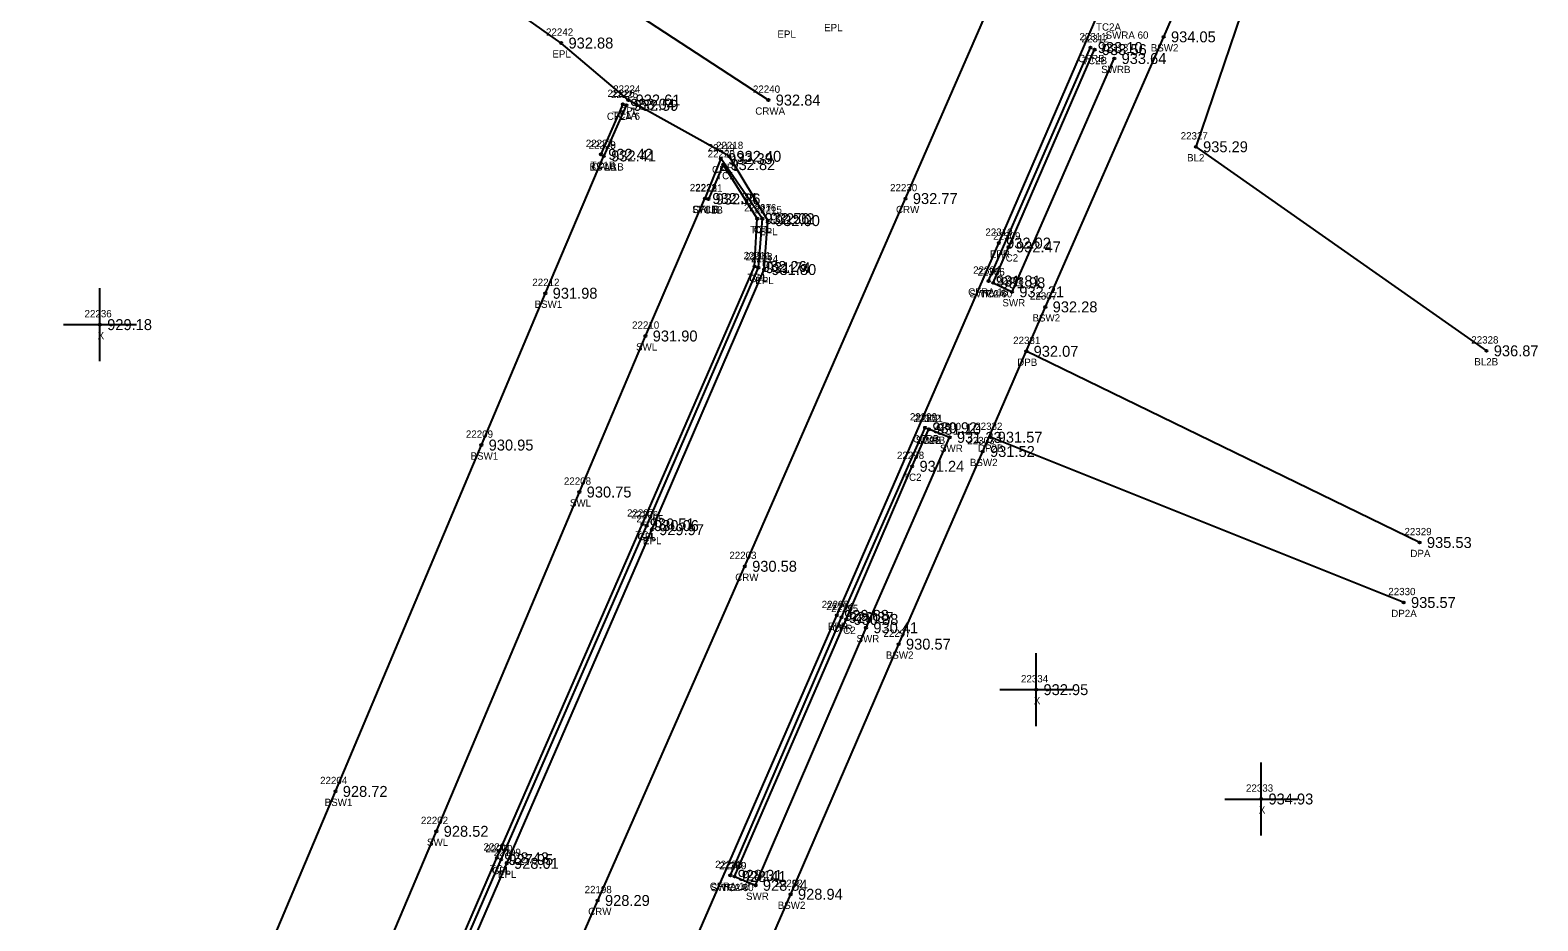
# Model space of a CAD drawing. Extents: x 1576181 to 1577685, y 1099396 to 1101490.
# Drawn here: x 1577213.8 to 1577420.4, y 1101221.4 to 1101343.5 of the extents above; entities that cross this region are included whole.
import ezdxf

# ---------------------------------------------------------------- set-up
doc = ezdxf.new("R2010")
doc.units = 0
for name, color, linetype in [('RD_DTM_BkLn1', 7, 'Continuous'), ('RD_DTM_BkLn2', 7, 'Continuous'), ('RD_DTM_BkLn_txCode', 7, 'Continuous'), ('RD_EX_Conc', 7, 'Continuous'), ('RD_EX_Conc_txCode', 7, 'Continuous'), ('RD_EX_Driveway', 7, 'Continuous'), ('RD_EX_Driveway_txCode', 7, 'Continuous'), ('RD_EX_Misc', 7, 'Continuous'), ('RD_EX_Misc_txCode', 7, 'Continuous'), ('RD_EX_Road', 7, 'Continuous'), ('RD_EX_Road_txCode', 7, 'Continuous'), ('RD_EX_TX_Conc_ELEV', 7, 'Continuous'), ('RD_EX_TX_Driveway_ELEV', 7, 'Continuous'), ('RD_EX_TX_Misc_ELEV', 7, 'Continuous'), ('RD_EX_TX_Road_ELEV', 7, 'Continuous'), ('RD_HC_Survey_ELEV', 7, 'Continuous'), ('RD_HC_Survey_txCode', 7, 'Continuous'), ('RD_SMD_Locator', 7, 'Continuous')]:
    doc.layers.add(name, color=color, linetype=linetype)

msp = doc.modelspace()

# ---------------------------------------------------------------- linework, layer by layer
at = {"layer": 'RD_DTM_BkLn1'}
for points in [[(1577315, 1101333.96), (1577292.13, 1101348.94), (1577251.18, 1101377.2), (1577210.87, 1101406.3), (1577169.7, 1101434.76), (1577128.91, 1101464.09)], [(1576908.25, 1100441.74), (1576920.44, 1100463.64), (1576944.47, 1100507.42), (1576973.89, 1100560.12), (1576993.13, 1100594.33), (1577014.77, 1100632.79), (1577042.14, 1100681.68), (1577066.82, 1100725.12), (1577089.75, 1100766.04), (1577111.87, 1100810.02), (1577132.74, 1100857.48), (1577152.58, 1100903.02), (1577172.32, 1100949.02), (1577191.93, 1100994.6), (1577211.77, 1101040.76), (1577222.24, 1101065.99), (1577231.17, 1101086.4), (1577251.41, 1101132.37), (1577271.56, 1101178.18), (1577291.61, 1101224.24), (1577311.77, 1101270.05), (1577333.79, 1101320.46), (1577355.93, 1101371.29), (1577365.01, 1101392.03)], [(1577390.63, 1101377.85), (1577373.56, 1101327.56), (1577413.39, 1101299.59)]]:
    msp.add_lwpolyline(points, dxfattribs=at)
at = {"layer": 'RD_DTM_BkLn2'}
msp.add_line((1577295.05, 1101333.39), (1577292.05, 1101326.53), dxfattribs=at)
for points in [[(1577345.79, 1101308.91), (1577347.93, 1101313.83), (1577359.7, 1101340.88)], [(1577230.41, 1101120.92), (1577237.86, 1101138.09), (1577257.81, 1101183.92), (1577277.8, 1101230.08), (1577297.74, 1101275.86), (1577313.11, 1101311.15), (1577313.47, 1101317.71), (1577308.8, 1101325.11), (1577306.78, 1101320.4)], [(1577310.35, 1101227.52), (1577325.67, 1101262.77), (1577334.7, 1101283.76), (1577336.99, 1101288.83)]]:
    msp.add_lwpolyline(points, dxfattribs=at)
at = {"layer": 'RD_EX_Conc'}
for p, q in [((1577345.17, 1101309.16), (1577359.13, 1101341.16)), ((1577295.52, 1101333.24), (1577292.45, 1101326.3))]:
    msp.add_line(p, q, dxfattribs=at)
for points in [[(1577253.83, 1101078.11), (1577273.62, 1101123.24), (1577293.57, 1101168.95), (1577318.05, 1101225.09), (1577332.85, 1101259.38), (1577344.37, 1101285.79), (1577352.95, 1101305.61), (1577369.16, 1101342.63), (1577386, 1101381.45)], [(1577345.79, 1101308.91), (1577348.38, 1101307.68), (1577362.39, 1101339.66)], [(1577183.3, 1101070.64), (1577191.17, 1101088.99), (1577203.3, 1101116.55), (1577216.89, 1101147.88), (1577236.17, 1101192.92), (1577255.68, 1101239.19), (1577275.67, 1101286.67), (1577284.44, 1101307.48), (1577292.45, 1101326.3)], [(1577230.94, 1101120.7), (1577238.39, 1101137.84), (1577258.38, 1101183.64), (1577278.38, 1101229.85), (1577298.33, 1101275.63), (1577313.63, 1101310.99), (1577314.18, 1101317.7), (1577308.48, 1101325.93), (1577306.31, 1101320.47)], [(1577226.68, 1101112.55), (1577219.31, 1101115.93), (1577230.24, 1101141.22), (1577249.76, 1101187.06), (1577269.51, 1101233.72), (1577289.1, 1101280.23), (1577298.15, 1101301.62), (1577306.31, 1101320.47)], [(1577309.79, 1101227.69), (1577325.01, 1101263.04), (1577336.47, 1101289.04)], [(1577310.35, 1101227.52), (1577313.24, 1101226.32), (1577328.38, 1101261.63), (1577339.83, 1101287.72), (1577336.99, 1101288.83)]]:
    msp.add_lwpolyline(points, dxfattribs=at)
at = {"layer": 'RD_EX_Driveway'}
for p, q in [((1577404.23, 1101273.31), (1577350.34, 1101299.52)), ((1577402.05, 1101265.09), (1577345.42, 1101287.75))]:
    msp.add_line(p, q, dxfattribs=at)
at = {"layer": 'RD_EX_Misc'}
for p, q in [((1577223.4, 1101298.18), (1577223.4, 1101308.18)), ((1577218.4, 1101303.18), (1577228.4, 1101303.18)), ((1577351.69, 1101248.14), (1577351.69, 1101258.14)), ((1577346.69, 1101253.14), (1577356.69, 1101253.14)), ((1577382.52, 1101233.15), (1577382.52, 1101243.15)), ((1577377.52, 1101238.15), (1577387.52, 1101238.15))]:
    msp.add_line(p, q, dxfattribs=at)
at = {"layer": 'RD_EX_Road'}
for points in [[(1577206.43, 1101064.72), (1577225.66, 1101106.5), (1577239.19, 1101137.5), (1577259.23, 1101183.34), (1577279.15, 1101229.33), (1577299.03, 1101275.07), (1577314.41, 1101310.73), (1577314.92, 1101317.44), (1577309.62, 1101326.25), (1577295.81, 1101333.97), (1577286.61, 1101341.78), (1577246.23, 1101370.35), (1577205.32, 1101399.1), (1577164.91, 1101427.55), (1577123.31, 1101456.71)], [(1577251.26, 1101061.34), (1577247.19, 1101065.51), (1577244.66, 1101070.88), (1577244.21, 1101077), (1577245.22, 1101081.73), (1577264.75, 1101126.91), (1577284.79, 1101172.93), (1577304.8, 1101218.29), (1577324.38, 1101263.32), (1577346.57, 1101314.36), (1577376.75, 1101384.19)]]:
    msp.add_lwpolyline(points, dxfattribs=at)
at = {"layer": 'RD_SMD_Locator'}
for centre in [(1577286.61, 1101341.78), (1577359.13, 1101341.16), (1577359.7, 1101340.88), (1577369.16, 1101342.63), (1577362.39, 1101339.66), (1577295.05, 1101333.39), (1577295.52, 1101333.24), (1577295.81, 1101333.97), (1577315, 1101333.96), (1577292.05, 1101326.53), (1577373.56, 1101327.56), (1577292.45, 1101326.3), (1577292.45, 1101326.3), (1577308.48, 1101325.93), (1577308.8, 1101325.11), (1577309.62, 1101326.25), (1577306.31, 1101320.47), (1577306.31, 1101320.47), (1577306.78, 1101320.4), (1577333.79, 1101320.46), (1577313.47, 1101317.71), (1577314.18, 1101317.7), (1577314.92, 1101317.44), (1577346.57, 1101314.36), (1577347.93, 1101313.83), (1577313.11, 1101311.15), (1577313.63, 1101310.99), (1577314.41, 1101310.73), (1577345.17, 1101309.16), (1577345.79, 1101308.91), (1577345.79, 1101308.91), (1577284.44, 1101307.48), (1577348.38, 1101307.68), (1577352.95, 1101305.61), (1577223.4, 1101303.18), (1577298.15, 1101301.62), (1577413.39, 1101299.59), (1577350.34, 1101299.52), (1577336.47, 1101289.04), (1577336.99, 1101288.83), (1577336.99, 1101288.83), (1577339.83, 1101287.72), (1577345.42, 1101287.75), (1577275.67, 1101286.67), (1577344.37, 1101285.79), (1577334.7, 1101283.76), (1577289.1, 1101280.23), (1577297.74, 1101275.86), (1577298.33, 1101275.63), (1577299.03, 1101275.07), (1577404.23, 1101273.31), (1577311.77, 1101270.05), (1577402.05, 1101265.09), (1577324.38, 1101263.32), (1577325.01, 1101263.04), (1577325.67, 1101262.77), (1577328.38, 1101261.63), (1577332.85, 1101259.38), (1577351.69, 1101253.14), (1577255.68, 1101239.19), (1577382.52, 1101238.15), (1577269.51, 1101233.72), (1577277.8, 1101230.08), (1577278.38, 1101229.85), (1577279.15, 1101229.33), (1577309.79, 1101227.69), (1577310.35, 1101227.52), (1577310.35, 1101227.52), (1577313.24, 1101226.32), (1577291.61, 1101224.24), (1577318.05, 1101225.09)]:
    msp.add_circle(centre, 0.15, dxfattribs=at)

# ---------------------------------------------------------------- texts
at = {"layer": 'RD_DTM_BkLn_txCode'}
for s, p in [('22327', (1577371.49, 1101328.56)), ('BL2', (1577372.36, 1101325.56)), ('22328', (1577411.31, 1101300.59)), ('BL2B', (1577411.72, 1101297.59))]:
    msp.add_text(s, height=1, dxfattribs=at).set_placement(p)
at = {"layer": 'RD_EX_Conc_txCode'}
for s, p in [('22311', (1577357.62, 1101342.16)), ('TC2A', (1577359.89, 1101343.48)), ('SWRA 60', (1577361.2, 1101342.37)), ('22312', (1577357.91, 1101341.88)), ('22313', (1577360.59, 1101340.66)), ('BSW2', (1577367.39, 1101340.63)), ('CFRB', (1577357.43, 1101339.16)), ('TC2B', (1577357.99, 1101338.88)), ('SWRB', (1577360.6, 1101337.66)), ('22226', (1577292.95, 1101334.39)), ('22225', (1577293.44, 1101334.24)), ('CFLA 6', (1577292.87, 1101331.24)), ('TC1A', (1577293.6, 1101331.39)), ('22227', (1577289.98, 1101327.53)), ('22228', (1577290.37, 1101327.3)), ('22229', (1577290.37, 1101327.3)), ('22219', (1577306.68, 1101326.93)), ('22220', (1577306.68, 1101326.11)), ('BSW1B', (1577290.5, 1101324.3)), ('TC1B', (1577290.62, 1101324.53)), ('CFLB', (1577290.77, 1101324.3)), ('CFL', (1577307.27, 1101323.93)), ('22222', (1577304.23, 1101321.47)), ('22223', (1577304.23, 1101321.47)), ('22221', (1577304.99, 1101321.4)), ('TC1', (1577307.84, 1101323.11)), ('SWLB', (1577304.55, 1101318.47)), ('CFLB', (1577304.64, 1101318.47)), ('TC1B', (1577305.35, 1101318.4)), ('22217', (1577311.67, 1101318.71)), ('22216', (1577312.36, 1101318.7)), ('TC1', (1577312.51, 1101315.71)), ('CFL', (1577312.98, 1101315.7)), ('22309', (1577345.81, 1101314.83)), ('22211', (1577311.6, 1101312.15)), ('22213', (1577311.84, 1101311.99)), ('TC2', (1577346.69, 1101311.83)), ('TC1', (1577312.15, 1101309.15)), ('22304', (1577343.06, 1101310.16)), ('22306', (1577343.65, 1101309.91)), ('22305', (1577343.68, 1101309.91)), ('22212', (1577282.65, 1101308.48)), ('CFL', (1577312.43, 1101308.99)), ('CFRA 18', (1577342.36, 1101307.16)), ('22308', (1577346.26, 1101308.68)), ('BSW1', (1577282.96, 1101305.48)), ('SWRA 60', (1577342.54, 1101306.91)), ('TC2A', (1577344.06, 1101306.91)), ('SWR', (1577347.06, 1101305.68)), ('22307', (1577350.83, 1101306.61)), ('BSW2', (1577351.18, 1101303.61)), ('22210', (1577296.32, 1101302.62)), ('SWL', (1577296.86, 1101299.62)), ('22299', (1577334.39, 1101290.04)), ('22302', (1577334.88, 1101289.83)), ('22301', (1577335.16, 1101289.83)), ('22300', (1577337.67, 1101288.72)), ('22209', (1577273.55, 1101287.67)), ('CFRB', (1577334.77, 1101287.04)), ('SWRB', (1577335.21, 1101286.83)), ('TC2B', (1577335.28, 1101286.83)), ('22303', (1577342.25, 1101286.79)), ('BSW1', (1577274.19, 1101284.67)), ('22298', (1577332.62, 1101284.76)), ('SWR', (1577338.51, 1101285.72)), ('BSW2', (1577342.61, 1101283.79)), ('22208', (1577286.98, 1101281.23)), ('TC2', (1577333.45, 1101281.76)), ('SWL', (1577287.8, 1101278.23)), ('22207', (1577295.63, 1101276.86)), ('22206', (1577296.19, 1101276.63)), ('TC1', (1577296.78, 1101273.86)), ('CFL', (1577297.12, 1101273.63)), ('22294', (1577322.93, 1101264.04)), ('22295', (1577323.59, 1101263.77)), ('22296', (1577326.28, 1101262.63)), ('CFR', (1577323.78, 1101261.04)), ('TC2', (1577324.43, 1101260.77)), ('SWR', (1577327.07, 1101259.63)), ('22297', (1577330.77, 1101260.38)), ('BSW2', (1577331.09, 1101257.38)), ('22204', (1577253.57, 1101240.19)), ('BSW1', (1577254.2, 1101237.19)), ('22202', (1577267.39, 1101234.72)), ('SWL', (1577268.22, 1101231.72)), ('22201', (1577275.96, 1101231.08)), ('22200', (1577276.22, 1101230.85)), ('22288', (1577307.71, 1101228.69)), ('22290', (1577308.24, 1101228.52)), ('22289', (1577308.28, 1101228.52)), ('TC1', (1577276.84, 1101228.08)), ('CFL', (1577277.17, 1101227.85)), ('22291', (1577311.45, 1101227.32)), ('CFRA 18', (1577306.97, 1101225.69)), ('SWRA 60', (1577307.1, 1101225.52)), ('TC2A', (1577308.62, 1101225.52)), ('SWR', (1577311.93, 1101224.32)), ('22292', (1577315.97, 1101226.09)), ('BSW2', (1577316.28, 1101223.09))]:
    msp.add_text(s, height=1, dxfattribs=at).set_placement(p)
at = {"layer": 'RD_EX_Driveway_txCode'}
for s, p in [('22331', (1577348.54, 1101300.52)), ('DPB', (1577349.09, 1101297.52)), ('22332', (1577343.34, 1101288.75)), ('DP2B', (1577343.72, 1101285.75)), ('22329', (1577402.15, 1101274.31)), ('DPA', (1577402.96, 1101271.31)), ('22330', (1577399.94, 1101266.09)), ('DP2A', (1577400.34, 1101263.09))]:
    msp.add_text(s, height=1, dxfattribs=at).set_placement(p)
at = {"layer": 'RD_EX_Misc_txCode'}
for s, p in [('22236', (1577221.3, 1101304.18)), ('X', (1577223.09, 1101301.18)), ('22334', (1577349.61, 1101254.14)), ('X', (1577351.37, 1101251.14)), ('22333', (1577380.44, 1101239.15)), ('X', (1577382.2, 1101236.15))]:
    msp.add_text(s, height=1, dxfattribs=at).set_placement(p)
at = {"layer": 'RD_EX_Road_txCode'}
for s, p in [('22242', (1577284.53, 1101342.78)), ('EPL', (1577316.23, 1101342.5)), ('EPL', (1577322.63, 1101343.4)), ('EPL', (1577285.4, 1101339.78)), ('22224', (1577293.73, 1101334.97)), ('EPL', (1577294.61, 1101331.97)), ('22218', (1577307.83, 1101327.25)), ('EPL', (1577308.42, 1101324.25)), ('22215', (1577313.13, 1101318.44)), ('EPL', (1577313.72, 1101315.44)), ('22310', (1577344.73, 1101315.36)), ('22214', (1577312.62, 1101311.73)), ('EPR', (1577345.34, 1101312.36)), ('EPL', (1577313.21, 1101308.73)), ('22205', (1577296.91, 1101276.07)), ('EPL', (1577297.82, 1101273.07)), ('22293', (1577322.3, 1101264.32)), ('EPR', (1577323.15, 1101261.32)), ('22199', (1577277.36, 1101230.33)), ('EPL', (1577277.95, 1101227.33))]:
    msp.add_text(s, height=1, dxfattribs=at).set_placement(p)
at = {"layer": 'RD_EX_TX_Conc_ELEV'}
for s, p in [('934.05', (1577370.16, 1101341.88)), ('933.10', (1577360.13, 1101340.41)), ('933.56', (1577360.7, 1101340.13)), ('933.64', (1577363.39, 1101338.91)), ('933.04', (1577296.05, 1101332.64)), ('932.59', (1577296.52, 1101332.49)), ('932.42', (1577293.05, 1101325.78)), ('932.41', (1577293.45, 1101325.55)), ('932.41', (1577293.45, 1101325.55)), ('932.39', (1577309.48, 1101325.18)), ('932.82', (1577309.8, 1101324.36)), ('932.34', (1577307.31, 1101319.72)), ('932.34', (1577307.31, 1101319.72)), ('932.36', (1577307.78, 1101319.65)), ('932.56', (1577314.47, 1101316.96)), ('932.02', (1577315.18, 1101316.95)), ('932.47', (1577348.93, 1101313.08)), ('932.26', (1577314.11, 1101310.4)), ('931.74', (1577314.63, 1101310.24)), ('931.98', (1577285.44, 1101306.73)), ('931.81', (1577346.17, 1101308.41)), ('931.98', (1577346.79, 1101308.16)), ('931.98', (1577346.79, 1101308.16)), ('932.21', (1577349.38, 1101306.93)), ('932.28', (1577353.95, 1101304.86)), ('931.90', (1577299.15, 1101300.87)), ('930.92', (1577337.47, 1101288.29)), ('931.10', (1577337.99, 1101288.08)), ('931.10', (1577337.99, 1101288.08)), ('930.95', (1577276.67, 1101285.92)), ('931.33', (1577340.83, 1101286.97)), ('931.52', (1577345.37, 1101285.04)), ('931.24', (1577335.7, 1101283.01)), ('930.75', (1577290.1, 1101279.48)), ('930.51', (1577298.74, 1101275.11)), ('930.06', (1577299.33, 1101274.88)), ('929.87', (1577326.01, 1101262.29)), ('930.38', (1577326.67, 1101262.02)), ('930.41', (1577329.38, 1101260.88)), ('930.57', (1577333.85, 1101258.63)), ('928.72', (1577256.68, 1101238.44)), ('928.52', (1577270.51, 1101232.97)), ('928.43', (1577278.8, 1101229.33)), ('927.95', (1577279.38, 1101229.1)), ('928.31', (1577310.79, 1101226.94)), ('928.41', (1577311.35, 1101226.77)), ('928.41', (1577311.35, 1101226.77)), ('928.84', (1577314.24, 1101225.57)), ('928.94', (1577319.05, 1101224.34))]:
    msp.add_text(s, height=1.5, dxfattribs=at).set_placement(p)
at = {"layer": 'RD_EX_TX_Driveway_ELEV'}
for s, p in [('932.07', (1577351.34, 1101298.77)), ('931.57', (1577346.42, 1101287)), ('935.53', (1577405.23, 1101272.56)), ('935.57', (1577403.05, 1101264.34))]:
    msp.add_text(s, height=1.5, dxfattribs=at).set_placement(p)
at = {"layer": 'RD_EX_TX_Misc_ELEV'}
for s, p in [('935.29', (1577374.56, 1101326.81)), ('929.18', (1577224.4, 1101302.43)), ('936.87', (1577414.39, 1101298.84)), ('932.95', (1577352.69, 1101252.39)), ('934.93', (1577383.52, 1101237.4))]:
    msp.add_text(s, height=1.5, dxfattribs=at).set_placement(p)
at = {"layer": 'RD_EX_TX_Road_ELEV'}
for s, p in [('932.88', (1577287.61, 1101341.03)), ('932.61', (1577296.81, 1101333.22)), ('932.40', (1577310.62, 1101325.5)), ('932.00', (1577315.92, 1101316.69)), ('932.02', (1577347.57, 1101313.61)), ('931.80', (1577315.41, 1101309.98)), ('929.97', (1577300.03, 1101274.32)), ('929.88', (1577325.38, 1101262.57)), ('928.01', (1577280.15, 1101228.58))]:
    msp.add_text(s, height=1.5, dxfattribs=at).set_placement(p)
at = {"layer": 'RD_HC_Survey_ELEV'}
for s, p in [('932.84', (1577316, 1101333.21)), ('932.77', (1577334.79, 1101319.71)), ('930.58', (1577312.77, 1101269.3)), ('928.29', (1577292.61, 1101223.49))]:
    msp.add_text(s, height=1.5, dxfattribs=at).set_placement(p)
at = {"layer": 'RD_HC_Survey_txCode'}
for s, p in [('22240', (1577312.88, 1101334.96)), ('CRWA', (1577313.2, 1101331.96)), ('22230', (1577331.67, 1101321.46)), ('CRW', (1577332.48, 1101318.46)), ('22203', (1577309.65, 1101271.05)), ('CRW', (1577310.45, 1101268.05)), ('22198', (1577289.82, 1101225.24)), ('CRW', (1577290.3, 1101222.24))]:
    msp.add_text(s, height=1, dxfattribs=at).set_placement(p)

doc.saveas('drawing.dxf')
